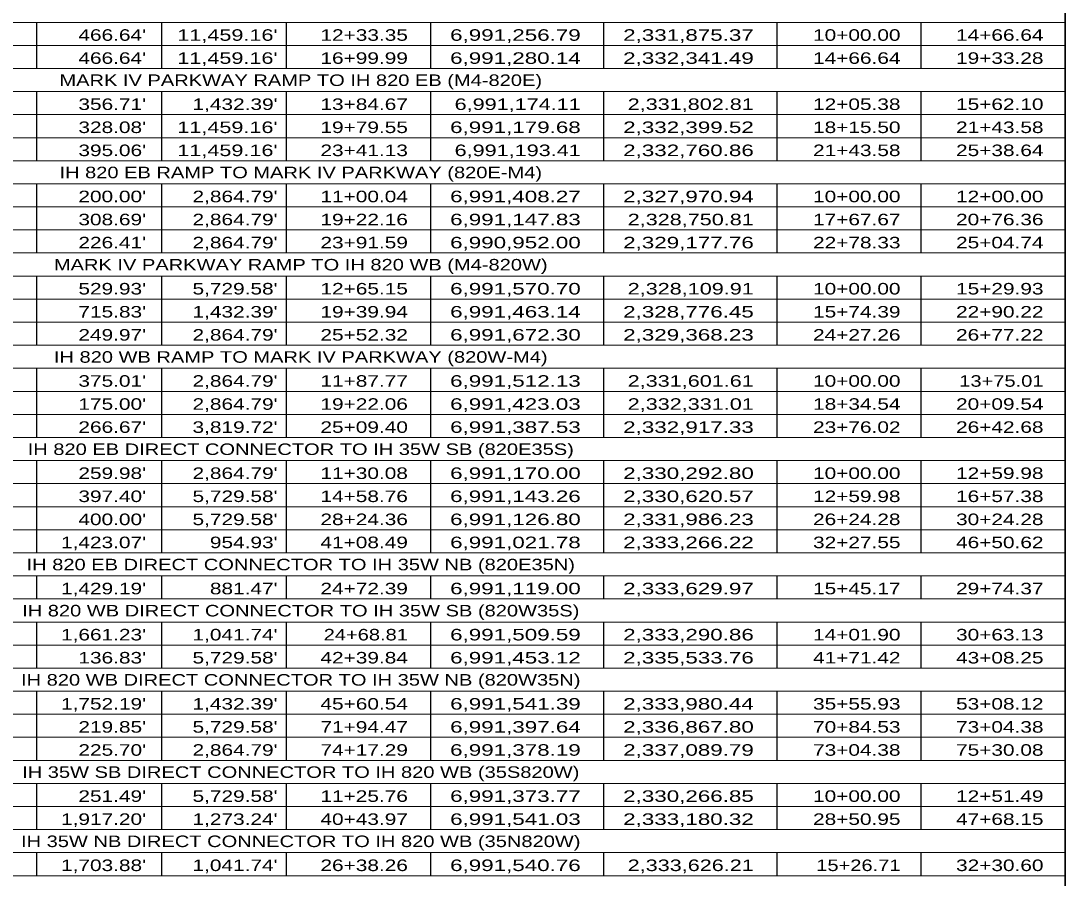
# Model space of a CAD drawing. Extents: x 1953053 to 1967065, y 7363860 to 7371201.
# Drawn here: x 1956571 to 1957657, y 7368493 to 7369385 of the extents above; entities that cross this region are included whole.
import ezdxf
from ezdxf.enums import TextEntityAlignment as Align

# ---------------------------------------------------------------- set-up
doc = ezdxf.new("R2010")
doc.units = 0
doc.header["$LTSCALE"] = 4.8
doc.layers.add('10', color=7, linetype='Continuous')
doc.layers.add('12', color=7, linetype='Continuous', lineweight=25)

msp = doc.modelspace()

# ---------------------------------------------------------------- linework, layer by layer
at = {"layer": '12', "lineweight": 35}
msp.add_line((1957656.717, 7367607.746), (1957656.717, 7370164.879), dxfattribs=at)
at = {"layer": '12', "lineweight": 13}
for p, q in [((1955933.385, 7369383.746), (1957656.717, 7369383.746)), ((1955933.385, 7369359.746), (1957656.717, 7369359.746)), ((1955933.385, 7369335.746), (1957656.717, 7369335.746)), ((1955933.385, 7369311.746), (1957656.717, 7369311.746)), ((1955933.385, 7369287.746), (1957656.717, 7369287.746)), ((1955933.385, 7369263.747), (1957656.717, 7369263.747)), ((1955933.385, 7369239.746), (1957656.717, 7369239.746)), ((1955933.385, 7369215.746), (1957656.717, 7369215.746)), ((1955933.385, 7369191.746), (1957656.717, 7369191.746)), ((1955933.385, 7369167.746), (1957656.717, 7369167.746)), ((1955933.385, 7369143.746), (1957656.717, 7369143.746)), ((1955933.385, 7369119.746), (1957656.717, 7369119.746)), ((1955933.385, 7369095.746), (1957656.717, 7369095.746)), ((1955933.385, 7369071.746), (1957656.717, 7369071.746)), ((1955933.385, 7369047.746), (1957656.717, 7369047.746)), ((1955933.385, 7369023.746), (1957656.717, 7369023.746)), ((1955933.385, 7368999.746), (1957656.717, 7368999.746)), ((1955933.385, 7368975.746), (1957656.717, 7368975.746)), ((1955933.385, 7368951.746), (1957656.717, 7368951.746)), ((1955933.385, 7368927.746), (1957656.717, 7368927.746)), ((1955933.385, 7368903.746), (1957656.717, 7368903.746)), ((1955933.385, 7368879.746), (1957656.717, 7368879.746)), ((1955933.385, 7368855.746), (1957656.717, 7368855.746)), ((1955933.385, 7368831.746), (1957656.717, 7368831.746)), ((1955933.385, 7368807.746), (1957656.717, 7368807.746)), ((1955933.385, 7368783.746), (1957656.717, 7368783.746)), ((1955933.385, 7368759.746), (1957656.717, 7368759.746)), ((1955933.385, 7368735.746), (1957656.717, 7368735.746)), ((1955933.385, 7368711.746), (1957656.717, 7368711.746)), ((1955933.385, 7368687.746), (1957656.717, 7368687.746)), ((1955933.385, 7368663.746), (1957656.717, 7368663.746)), ((1955933.385, 7368639.746), (1957656.717, 7368639.746)), ((1955933.385, 7368615.746), (1957656.717, 7368615.746)), ((1955933.385, 7368591.746), (1957656.717, 7368591.746)), ((1955933.385, 7368567.746), (1957656.717, 7368567.746)), ((1955933.385, 7368543.746), (1957656.717, 7368543.746)), ((1955933.385, 7368519.746), (1957656.717, 7368519.746)), ((1955933.385, 7368495.746), (1957656.717, 7368495.746))]:
    msp.add_line(p, q, dxfattribs=at)
at = {"layer": '12'}
for p, q in [((1956586.717, 7369383.746), (1956586.717, 7369335.746)), ((1956716.717, 7369383.746), (1956716.717, 7369335.746)), ((1956846.717, 7369383.746), (1956846.717, 7369335.746)), ((1956996.717, 7369383.746), (1956996.717, 7369335.746)), ((1957176.717, 7369383.746), (1957176.717, 7369335.746)), ((1957356.717, 7369383.746), (1957356.717, 7369335.746)), ((1957506.717, 7369383.746), (1957506.717, 7369335.746)), ((1956586.717, 7369311.746), (1956586.717, 7369239.746)), ((1956716.717, 7369311.746), (1956716.717, 7369239.746)), ((1956846.717, 7369311.746), (1956846.717, 7369239.746)), ((1956996.717, 7369311.746), (1956996.717, 7369239.746)), ((1957176.717, 7369311.746), (1957176.717, 7369239.746)), ((1957356.717, 7369311.746), (1957356.717, 7369239.746)), ((1957506.717, 7369311.746), (1957506.717, 7369239.746)), ((1956586.717, 7369215.746), (1956586.717, 7369143.746)), ((1956716.717, 7369215.746), (1956716.717, 7369143.746)), ((1956846.717, 7369215.746), (1956846.717, 7369143.746)), ((1956996.717, 7369215.746), (1956996.717, 7369143.746)), ((1957176.717, 7369215.746), (1957176.717, 7369143.746)), ((1957356.717, 7369215.746), (1957356.717, 7369143.746)), ((1957506.717, 7369215.746), (1957506.717, 7369143.746)), ((1956586.717, 7369119.746), (1956586.717, 7369047.746)), ((1956716.717, 7369119.746), (1956716.717, 7369047.746)), ((1956846.717, 7369119.746), (1956846.717, 7369047.746)), ((1956996.717, 7369119.746), (1956996.717, 7369047.746)), ((1957176.717, 7369119.746), (1957176.717, 7369047.746)), ((1957356.717, 7369119.746), (1957356.717, 7369047.746)), ((1957506.717, 7369119.746), (1957506.717, 7369047.746)), ((1956586.717, 7369023.746), (1956586.717, 7368951.746)), ((1956716.717, 7369023.746), (1956716.717, 7368951.746)), ((1956846.717, 7369023.746), (1956846.717, 7368951.746)), ((1956996.717, 7369023.746), (1956996.717, 7368951.746)), ((1957176.717, 7369023.746), (1957176.717, 7368951.746)), ((1957356.717, 7369023.746), (1957356.717, 7368951.746)), ((1957506.717, 7369023.746), (1957506.717, 7368951.746)), ((1956586.717, 7368927.746), (1956586.717, 7368831.746)), ((1956716.717, 7368927.746), (1956716.717, 7368831.746)), ((1956846.717, 7368927.746), (1956846.717, 7368831.746)), ((1956996.717, 7368927.746), (1956996.717, 7368831.746)), ((1957176.717, 7368927.746), (1957176.717, 7368831.746)), ((1957356.717, 7368927.746), (1957356.717, 7368831.746)), ((1957506.717, 7368927.746), (1957506.717, 7368831.746)), ((1956586.717, 7368807.746), (1956586.717, 7368783.746)), ((1956716.717, 7368807.746), (1956716.717, 7368783.746)), ((1956846.717, 7368807.746), (1956846.717, 7368783.746)), ((1956996.717, 7368807.746), (1956996.717, 7368783.746)), ((1957176.717, 7368807.746), (1957176.717, 7368783.746)), ((1957356.717, 7368807.746), (1957356.717, 7368783.746)), ((1957506.717, 7368807.746), (1957506.717, 7368783.746)), ((1956586.717, 7368759.746), (1956586.717, 7368711.746)), ((1956716.717, 7368759.746), (1956716.717, 7368711.746)), ((1956846.717, 7368759.746), (1956846.717, 7368711.746)), ((1956996.717, 7368759.746), (1956996.717, 7368711.746)), ((1957176.717, 7368759.746), (1957176.717, 7368711.746)), ((1957356.717, 7368759.746), (1957356.717, 7368711.746)), ((1957506.717, 7368759.746), (1957506.717, 7368711.746)), ((1956586.717, 7368687.746), (1956586.717, 7368615.746)), ((1956716.717, 7368687.746), (1956716.717, 7368615.746)), ((1956846.717, 7368687.746), (1956846.717, 7368615.746)), ((1956996.717, 7368687.746), (1956996.717, 7368615.746)), ((1957176.717, 7368687.746), (1957176.717, 7368615.746)), ((1957356.717, 7368687.746), (1957356.717, 7368615.746)), ((1957506.717, 7368687.746), (1957506.717, 7368615.746)), ((1956586.717, 7368591.746), (1956586.717, 7368543.746)), ((1956716.717, 7368591.746), (1956716.717, 7368543.746)), ((1956846.717, 7368591.746), (1956846.717, 7368543.746)), ((1956996.717, 7368591.746), (1956996.717, 7368543.746)), ((1957176.717, 7368591.746), (1957176.717, 7368543.746)), ((1957356.717, 7368591.746), (1957356.717, 7368543.746)), ((1957506.717, 7368591.746), (1957506.717, 7368543.746)), ((1956586.717, 7368519.746), (1956586.717, 7368495.746)), ((1956716.717, 7368519.746), (1956716.717, 7368495.746)), ((1956846.717, 7368519.746), (1956846.717, 7368495.746)), ((1956996.717, 7368519.746), (1956996.717, 7368495.746)), ((1957176.717, 7368519.746), (1957176.717, 7368495.746)), ((1957356.717, 7368519.746), (1957356.717, 7368495.746)), ((1957506.717, 7368519.746), (1957506.717, 7368495.746))]:
    msp.add_line(p, q, dxfattribs=at)

# ---------------------------------------------------------------- texts
at = {"layer": '10'}
for s, width, p in [("466.64'", 1.35, (1956700.841, 7369364.573)), ("11,459.16'", 1.4, (1956837.61, 7369364.573)), ('12+33.35', 1.35, (1956973.154, 7369364.573)), ('6,991,256.79', 1.45, (1957152.919, 7369364.573)), ('2,331,875.37', 1.45, (1957332.919, 7369364.573)), ('10+00.00', 1.35, (1957485.497, 7369364.573)), ('14+66.64', 1.35, (1957634.229, 7369364.573)), ("466.64'", 1.35, (1956700.841, 7369340.573)), ("11,459.16'", 1.4, (1956837.61, 7369340.573)), ('16+99.99', 1.35, (1956973.154, 7369340.573)), ('6,991,280.14', 1.45, (1957152.919, 7369340.573)), ('2,332,341.49', 1.45, (1957332.919, 7369340.573)), ('14+66.64', 1.35, (1957485.497, 7369340.573)), ('19+33.28', 1.35, (1957634.229, 7369340.573)), ("356.71'", 1.35, (1956700.846, 7369292.569)), ("1,432.39'", 1.35, (1956837.615, 7369292.569)), ('13+84.67', 1.35, (1956973.159, 7369292.569)), ('6,991,174.11', 1.4, (1957152.924, 7369292.569)), ('2,331,802.81', 1.4, (1957332.924, 7369292.569)), ('12+05.38', 1.35, (1957485.502, 7369292.569)), ('15+62.10', 1.35, (1957634.234, 7369292.569)), ("328.08'", 1.35, (1956700.846, 7369268.569)), ("11,459.16'", 1.4, (1956837.615, 7369268.569)), ('19+79.55', 1.35, (1956973.159, 7369268.569)), ('6,991,179.68', 1.45, (1957152.924, 7369268.569)), ('2,332,399.52', 1.45, (1957332.924, 7369268.569)), ('18+15.50', 1.35, (1957485.502, 7369268.569)), ('21+43.58', 1.35, (1957634.234, 7369268.569)), ("395.06'", 1.35, (1956700.846, 7369244.569)), ("11,459.16'", 1.4, (1956837.615, 7369244.569)), ('23+41.13', 1.35, (1956973.159, 7369244.569)), ('6,991,193.41', 1.4, (1957152.924, 7369244.569)), ('2,332,760.86', 1.45, (1957332.924, 7369244.569)), ('21+43.58', 1.35, (1957485.502, 7369244.569)), ('25+38.64', 1.35, (1957634.234, 7369244.569)), ("200.00'", 1.35, (1956700.846, 7369196.569)), ("2,864.79'", 1.35, (1956837.615, 7369196.569)), ('11+00.04', 1.35, (1956973.159, 7369196.569)), ('6,991,408.27', 1.45, (1957152.924, 7369196.569)), ('2,327,970.94', 1.45, (1957332.924, 7369196.569)), ('10+00.00', 1.35, (1957485.502, 7369196.569)), ('12+00.00', 1.35, (1957634.234, 7369196.569)), ("308.69'", 1.35, (1956700.846, 7369172.569)), ("2,864.79'", 1.35, (1956837.615, 7369172.569)), ('19+22.16', 1.35, (1956973.159, 7369172.569)), ('6,991,147.83', 1.45, (1957152.924, 7369172.569)), ('2,328,750.81', 1.4, (1957332.924, 7369172.569)), ('17+67.67', 1.35, (1957485.502, 7369172.569)), ('20+76.36', 1.35, (1957634.234, 7369172.569)), ("226.41'", 1.35, (1956700.846, 7369148.569)), ("2,864.79'", 1.35, (1956837.615, 7369148.569)), ('23+91.59', 1.35, (1956973.159, 7369148.569)), ('6,990,952.00', 1.45, (1957152.924, 7369148.569)), ('2,329,177.76', 1.45, (1957332.924, 7369148.569)), ('22+78.33', 1.35, (1957485.502, 7369148.569)), ('25+04.74', 1.35, (1957634.234, 7369148.569)), ("529.93'", 1.35, (1956700.846, 7369100.569)), ("5,729.58'", 1.35, (1956837.615, 7369100.569)), ('12+65.15', 1.35, (1956973.159, 7369100.569)), ('6,991,570.70', 1.45, (1957152.924, 7369100.569)), ('2,328,109.91', 1.4, (1957332.924, 7369100.569)), ('10+00.00', 1.35, (1957485.502, 7369100.569)), ('15+29.93', 1.35, (1957634.234, 7369100.569)), ("715.83'", 1.35, (1956700.846, 7369076.569)), ("1,432.39'", 1.35, (1956837.615, 7369076.569)), ('19+39.94', 1.35, (1956973.159, 7369076.569)), ('6,991,463.14', 1.45, (1957152.924, 7369076.569)), ('2,328,776.45', 1.45, (1957332.924, 7369076.569)), ('15+74.39', 1.35, (1957485.502, 7369076.569)), ('22+90.22', 1.35, (1957634.234, 7369076.569)), ("249.97'", 1.35, (1956700.846, 7369052.569)), ("2,864.79'", 1.35, (1956837.615, 7369052.569)), ('25+52.32', 1.35, (1956973.159, 7369052.569)), ('6,991,672.30', 1.45, (1957152.924, 7369052.569)), ('2,329,368.23', 1.45, (1957332.924, 7369052.569)), ('24+27.26', 1.35, (1957485.502, 7369052.569)), ('26+77.22', 1.35, (1957634.234, 7369052.569)), ("375.01'", 1.35, (1956700.846, 7369004.569)), ("2,864.79'", 1.35, (1956837.615, 7369004.569)), ('11+87.77', 1.35, (1956973.159, 7369004.569)), ('6,991,512.13', 1.45, (1957152.924, 7369004.569)), ('2,331,601.61', 1.4, (1957332.924, 7369004.569)), ('10+00.00', 1.35, (1957485.502, 7369004.569)), ('13+75.01', 1.3, (1957634.234, 7369004.569)), ("175.00'", 1.35, (1956700.846, 7368980.569)), ("2,864.79'", 1.35, (1956837.615, 7368980.569)), ('19+22.06', 1.35, (1956973.159, 7368980.569)), ('6,991,423.03', 1.45, (1957152.924, 7368980.569)), ('2,332,331.01', 1.4, (1957332.924, 7368980.569)), ('18+34.54', 1.35, (1957485.502, 7368980.569)), ('20+09.54', 1.35, (1957634.234, 7368980.569)), ("266.67'", 1.35, (1956700.846, 7368956.569)), ("3,819.72'", 1.35, (1956837.615, 7368956.569)), ('25+09.40', 1.35, (1956973.159, 7368956.569)), ('6,991,387.53', 1.45, (1957152.924, 7368956.569)), ('2,332,917.33', 1.45, (1957332.924, 7368956.569)), ('23+76.02', 1.35, (1957485.502, 7368956.569)), ('26+42.68', 1.35, (1957634.234, 7368956.569)), ("259.98'", 1.35, (1956700.846, 7368908.569)), ("2,864.79'", 1.35, (1956837.615, 7368908.569)), ('11+30.08', 1.35, (1956973.159, 7368908.569)), ('6,991,170.00', 1.45, (1957152.924, 7368908.569)), ('2,330,292.80', 1.45, (1957332.924, 7368908.569)), ('10+00.00', 1.35, (1957485.502, 7368908.569)), ('12+59.98', 1.35, (1957634.234, 7368908.569)), ("397.40'", 1.35, (1956700.846, 7368884.569)), ("5,729.58'", 1.35, (1956837.615, 7368884.569)), ('14+58.76', 1.35, (1956973.159, 7368884.569)), ('6,991,143.26', 1.45, (1957152.924, 7368884.569)), ('2,330,620.57', 1.45, (1957332.924, 7368884.569)), ('12+59.98', 1.35, (1957485.502, 7368884.569)), ('16+57.38', 1.35, (1957634.234, 7368884.569)), ("400.00'", 1.35, (1956700.846, 7368860.569)), ("5,729.58'", 1.35, (1956837.615, 7368860.569)), ('28+24.36', 1.35, (1956973.159, 7368860.569)), ('6,991,126.80', 1.45, (1957152.924, 7368860.569)), ('2,331,986.23', 1.45, (1957332.924, 7368860.569)), ('26+24.28', 1.35, (1957485.502, 7368860.569)), ('30+24.28', 1.35, (1957634.234, 7368860.569)), ("1,423.07'", 1.35, (1956700.846, 7368836.569)), ("954.93'", 1.35, (1956837.615, 7368836.569)), ('41+08.49', 1.35, (1956973.159, 7368836.569)), ('6,991,021.78', 1.45, (1957152.924, 7368836.569)), ('2,333,266.22', 1.45, (1957332.924, 7368836.569)), ('32+27.55', 1.35, (1957485.502, 7368836.569)), ('46+50.62', 1.35, (1957634.234, 7368836.569)), ("1,429.19'", 1.35, (1956700.846, 7368788.569)), ("881.47'", 1.35, (1956837.615, 7368788.569)), ('24+72.39', 1.35, (1956973.159, 7368788.569)), ('6,991,119.00', 1.45, (1957152.924, 7368788.569)), ('2,333,629.97', 1.45, (1957332.924, 7368788.569)), ('15+45.17', 1.35, (1957485.502, 7368788.569)), ('29+74.37', 1.35, (1957634.234, 7368788.569)), ("1,661.23'", 1.35, (1956700.846, 7368740.569)), ("1,041.74'", 1.35, (1956837.615, 7368740.569)), ('24+68.81', 1.3, (1956973.159, 7368740.569)), ('6,991,509.59', 1.45, (1957152.924, 7368740.569)), ('2,333,290.86', 1.45, (1957332.924, 7368740.569)), ('14+01.90', 1.35, (1957485.502, 7368740.569)), ('30+63.13', 1.35, (1957634.234, 7368740.569)), ("136.83'", 1.35, (1956700.846, 7368716.569)), ("5,729.58'", 1.35, (1956837.615, 7368716.569)), ('42+39.84', 1.35, (1956973.159, 7368716.569)), ('6,991,453.12', 1.45, (1957152.924, 7368716.569)), ('2,335,533.76', 1.45, (1957332.924, 7368716.569)), ('41+71.42', 1.35, (1957485.502, 7368716.569)), ('43+08.25', 1.35, (1957634.234, 7368716.569)), ("1,752.19'", 1.35, (1956700.846, 7368668.569)), ("1,432.39'", 1.35, (1956837.615, 7368668.569)), ('45+60.54', 1.35, (1956973.159, 7368668.569)), ('6,991,541.39', 1.45, (1957152.924, 7368668.569)), ('2,333,980.44', 1.45, (1957332.924, 7368668.569)), ('35+55.93', 1.35, (1957485.502, 7368668.569)), ('53+08.12', 1.35, (1957634.234, 7368668.569)), ("219.85'", 1.35, (1956700.846, 7368644.569)), ("5,729.58'", 1.35, (1956837.615, 7368644.569)), ('71+94.47', 1.35, (1956973.159, 7368644.569)), ('6,991,397.64', 1.45, (1957152.924, 7368644.569)), ('2,336,867.80', 1.45, (1957332.924, 7368644.569)), ('70+84.53', 1.35, (1957485.502, 7368644.569)), ('73+04.38', 1.35, (1957634.234, 7368644.569)), ("225.70'", 1.35, (1956700.846, 7368620.569)), ("2,864.79'", 1.35, (1956837.615, 7368620.569)), ('74+17.29', 1.35, (1956973.159, 7368620.569)), ('6,991,378.19', 1.45, (1957152.924, 7368620.569)), ('2,337,089.79', 1.45, (1957332.924, 7368620.569)), ('73+04.38', 1.35, (1957485.502, 7368620.569)), ('75+30.08', 1.35, (1957634.234, 7368620.569)), ("251.49'", 1.35, (1956700.846, 7368572.569)), ("5,729.58'", 1.35, (1956837.615, 7368572.569)), ('11+25.76', 1.35, (1956973.159, 7368572.569)), ('6,991,373.77', 1.45, (1957152.924, 7368572.569)), ('2,330,266.85', 1.45, (1957332.924, 7368572.569)), ('10+00.00', 1.35, (1957485.502, 7368572.569)), ('12+51.49', 1.35, (1957634.234, 7368572.569)), ("1,917.20'", 1.35, (1956700.846, 7368548.569)), ("1,273.24'", 1.35, (1956837.615, 7368548.569)), ('40+43.97', 1.35, (1956973.159, 7368548.569)), ('6,991,541.03', 1.45, (1957152.924, 7368548.569)), ('2,333,180.32', 1.45, (1957332.924, 7368548.569)), ('28+50.95', 1.35, (1957485.502, 7368548.569)), ('47+68.15', 1.35, (1957634.234, 7368548.569)), ("1,703.88'", 1.35, (1956700.846, 7368500.569)), ("1,041.74'", 1.35, (1956837.615, 7368500.569)), ('26+38.26', 1.35, (1956973.159, 7368500.569)), ('6,991,540.76', 1.45, (1957152.924, 7368500.569)), ('2,333,626.21', 1.4, (1957332.924, 7368500.569)), ('15+26.71', 1.3, (1957485.502, 7368500.569)), ('32+30.60', 1.35, (1957634.234, 7368500.569))]:
    msp.add_text(s, height=12, dxfattribs=dict(at, width=width)).set_placement(p, align=Align.RIGHT)
at = {"layer": '10', "width": 1.3}
for s, p in [('MARK IV PARKWAY RAMP TO IH 820 EB (M4-820E)', (1956861.717, 7369317.54)), ('IH 820 EB RAMP TO MARK IV PARKWAY (820E-M4)', (1956861.717, 7369221.54)), ('MARK IV PARKWAY RAMP TO IH 820 WB (M4-820W)', (1956861.717, 7369125.54)), ('IH 820 WB RAMP TO MARK IV PARKWAY (820W-M4)', (1956861.717, 7369029.54)), ('IH 820 EB DIRECT CONNECTOR TO IH 35W SB (820E35S)', (1956861.717, 7368933.54)), ('IH 820 EB DIRECT CONNECTOR TO IH 35W NB (820E35N)', (1956861.717, 7368813.54)), ('IH 820 WB DIRECT CONNECTOR TO IH 35W SB (820W35S)', (1956861.717, 7368765.54)), ('IH 820 WB DIRECT CONNECTOR TO IH 35W NB (820W35N)', (1956861.717, 7368693.54)), ('IH 35W SB DIRECT CONNECTOR TO IH 820 WB (35S820W)', (1956861.717, 7368597.54)), ('IH 35W NB DIRECT CONNECTOR TO IH 820 WB (35N820W)', (1956861.717, 7368525.54))]:
    msp.add_text(s, height=12, dxfattribs=at).set_placement(p, align=Align.CENTER)

doc.saveas('drawing.dxf')
